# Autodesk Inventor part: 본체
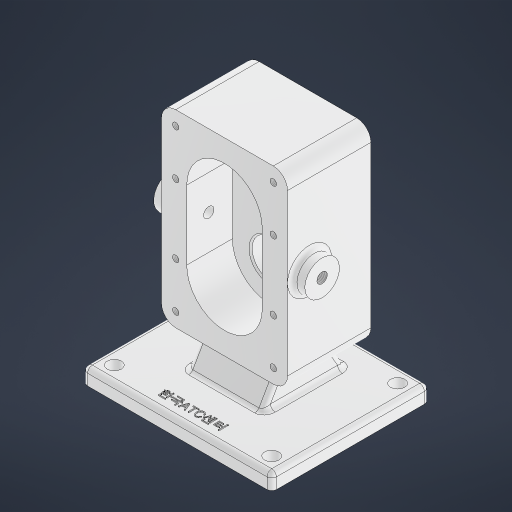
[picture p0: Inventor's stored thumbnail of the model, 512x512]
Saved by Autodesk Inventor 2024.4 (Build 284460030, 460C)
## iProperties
Created: 2026-10
Part Number: 본체
Material: 알루미늄 6061
Document SubType Name: Modeling
Designer: user
Density: 2.7 g/cm^3
Appearance: 알루미늄 - 평지
Mass: 1476.64 g
Surface Area: 830.225 cm^2
Volume: 546.904 cm^3
Author: user
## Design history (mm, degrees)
sketch "스케치1"
  geometry: L1 (-40, -26.5)-(40, -26.5); L2 (40, -26.5)-(40, 26.5); L3 (40, 26.5)-(-40, 26.5); L4 (-40, 26.5)-(-40, -26.5); L5 (-40, -26.5)-(40, 26.5); L6 (40, -26.5)-(-40, 26.5); 1 further point
  constraints: 12 end point, 2 midpoint, 2 parallel, 1 horizontal, 1 perpendicular
  dimensions: "d2" = 80 distance of L3.end L2.end; "d3" = 53 distance of L2.end L1.end
extrude "돌출1" new body sketch "스케치1" stored distance "d4" = 120; taper "d5" = 0 deg
fillet "모깎기1" dims "d6" = 9
sketch "스케치2"
  geometry: L1 (31, 38)-(31, 82); L2 (7, 38)-(7, 82); L3 (55, 82)-(55, 38); A1 r 24 centre (31, 38) between (7, 38) and (55, 38); A2 r 24 centre (31, 82) between (55, 82) and (7, 82); 3 further points
  constraints: 8 end point, 6 point on circle, 4 tangent, 2 centre point, 1 midpoint, 1 parallel, 1 vertical
  dimensions: "d7" = 48 distance between parallel lines of L2 L3; "d8" = 92 distance of point (31, 14) point (31, 106)
extrude "돌출2" cut sketch "스케치2" distance "d9" = 29; taper "d10" = 0 deg
sketch "스케치3"
  geometry: C1 r 12.5 at (31, 82); C2 r 12.5 at (31, 38); A1 r 24 centre (31, 38) between (7, 38) and (55, 38) reference; A2 r 24 centre (31, 82) between (55, 82) and (7, 82) reference; 1 further point
  constraints: 2 centre point, 2 coincident
  dimensions: "d11" = 25 diameter of C1; "d12" = 25 diameter of C2
extrude "돌출3" cut sketch "스케치3" distance "d13" = 15; taper "d14" = 0 deg
sketch "스케치4"
  geometry: C1 r 12.5 at (31, 38) reference; C2 r 19 at (31, 38); 1 further point
  constraints: 1 centre point, 1 coincident
  dimensions: "d15" = 38 diameter of C2
extrude "돌출4" join sketch "스케치4" distance "d16" = 17; taper "d17" = 0 deg
sketch "스케치5"
  geometry: C1 r 19 at (0, 0) reference; C2 r 14 at (0, 0); 1 further point
  constraints: 1 centre point, 1 coincident
  dimensions: "d18" = 28 diameter of C2
extrude "돌출5" cut sketch "스케치5" distance "d19" = 7.3; taper "d20" = 0 deg
sketch "스케치6"
  geometry: C1 r 12.5 at (0, 0) reference; C2 r 8.5 at (0, 0); 1 further point
  constraints: 1 centre point, 1 coincident
  dimensions: "d21" = 17 diameter of C2
extrude "돌출6" cut sketch "스케치6" distance "d22" = 29; taper "d23" = 0 deg
node "작업 평면1"
sketch "스케치9"
  geometry: L1 (19, 43.5)-(-19, 43.5) reference; L2 (60, -56.5)-(-60, -56.5); L3 (-60, -56.5)-(-60, 43.5); L4 (-60, 43.5)-(60, 43.5); L5 (60, 43.5)-(60, -56.5); L6 (60, -56.5)-(-60, 43.5); L7 (-60, -56.5)-(60, 43.5); 5 further points
  constraints: 12 end point, 4 midpoint, 2 parallel, 1 horizontal, 1 perpendicular, 1 vertical alignment
  dimensions: "d28" = 120 distance of L3.end L4.end; "d29" = 100 distance of L2.end L3.end
extrude "돌출7" join sketch "스케치9" distance "d30" = 10; taper "d31" = 0 deg
sketch "스케치10"
  geometry: L1 (-26.5, -60)-(26.5, -60) reference; L2 (-56.5, -80)-(43.5, -80) reference; L3 (43.5, -80)-(-56.5, -80) reference; L4 (-14.953, -60)-(-26.5, -80); L5 (14.953, -60)-(26.5, -80); L6 (43.5, -90)-(43.5, -80) reference; 3 further points
  constraints: 4 end point, 4 point on line
  dimensions: "d32" = 60 deg angle of L2 L4; "d33" = 60 deg angle of L2 L5; "d34" = 53 distance of L5.end L4.end; "d35" = 17 distance from line of L6 L5.end
extrude "돌출8" join sketch "스케치10" stored distance "d36" = 48; taper "d37" = 0 deg
sketch "스케치11"
  geometry: L1 (-102, 0)-(0, 0) reference; C1 r 11 at (-51, 14); 1 further point
  constraints: 1 centre point, 1 vertical alignment
  dimensions: "d39" = 22 diameter of C1; "d40" = 14 distance from line of L1 C1.centre
extrude "돌출9" join sketch "스케치11" distance "d41" = 8; taper "d42" = 0 deg
sketch "스케치12"
  geometry: L1 (60, -56.5)-(60, 43.5) reference; L2 (60, 43.5)-(-60, 43.5) reference; C1 r 4.5 at (-50, 33.5); C2 r 4.5 at (50, 33.5); C3 r 4.5 at (-50, -46.5); C4 r 4.5 at (50, -46.5); 1 further point
  constraints: 4 centre point, 2 horizontal alignment, 2 vertical alignment
  dimensions: "d43" = 9 diameter of C1; "d44" = 9 diameter of C2; "d45" = 9 diameter of C3; "d46" = 9 diameter of C4; "d47" = 100 distance of C2.centre C1.centre; "d48" = 10 distance from line of L1 C2.centre; "d49" = 80 distance of C4.centre C2.centre; "d50" = 10 distance from line of L2 C2.centre
fillet "모깎기2" dims "d51" = 3
fillet "모깎기3" dims "d52" = 3
hole "구멍1" sketch "스케치12" diameter "d53" = 9; stored, may be unused: countersink angle "d57" = 90 deg, drill point angle "d59" = 118 deg; dims "d54" = 6, "d55" = 10, "d56" = 5.5, "d58" = 8
sketch "스케치13"
  geometry: A1 r 9 centre (0, 9) between (-9, 9) and (0, 0) reference; A2 r 9 centre (62, 9) between (62, 0) and (71, 9) reference; A3 r 9 centre (62, 111) between (71, 111) and (62, 120) reference; 9 further points
  constraints: 4 vertical alignment, 3 coincident, 3 horizontal alignment
  dimensions: "d60" = 62 distance of point (62, 111) point (0, 111); "d61" = 29 distance of point (62, 82) point (62, 111); "d63" = 29 distance of point (62, 9) point (62, 38)
hole "구멍2" sketch "스케치13" at (0, 111), (62, 111), (62, 82), (0, 82), (0, 38), (62, 38), (62, 9), (0, 9) diameter "d64" = 4.134; stored, may be unused: countersink angle "d68" = 90 deg, drill point angle "d70" = 118 deg; dims "d65" = 10, "d66" = 5, "d67" = 2, "d69" = 12
sketch "스케치14"
  geometry: L1 (-57, -56.5)-(57, -56.5) reference; 2 further points
  constraints: 1 vertical alignment, 1 other
  dimensions: "d71" = 10 distance from line of point (0, -46.5) L1
sketch "스케치16"
  geometry: C1 r 11 at (0, 0) reference; 2 further points
  constraints: 1 coincident
hole "구멍3" sketch "스케치16" at (0, 0) diameter "d72" = 6.647; stored, may be unused: countersink angle "d76" = 90 deg, drill point angle "d78" = 0 deg; dims "d73" = 8, "d74" = 4, "d75" = 2, "d77" = 24
chamfer "모따기1" distance "d79" = 1; stored, may be unused: second distance "d80" = 2, angle "d81" = 45 deg
fillet "모깎기4" dims "d82" = 0.5
chamfer "모따기2" distance "d83" = 0.7; stored, may be unused: second distance "d84" = 2, angle "d85" = 30 deg
feature "엠보싱1" dims "d2" = 80, "d3" = 53, "d86" = 0.5, "d87" = 0
fillet "모깎기5" dims "d88" = 3
fillet "모깎기6" dims "d89" = 3
sketch "스케치17"
  geometry: C1 r 11 at (0, 0) reference; 2 further points
  constraints: 1 coincident
hole "구멍4" sketch "스케치17" at (0, 0) diameter "d90" = 6.647; stored, may be unused: countersink angle "d94" = 90 deg, drill point angle "d96" = 0 deg; dims "d91" = 8, "d92" = 4, "d93" = 2, "d95" = 24
node "솔리드1"
mirror "미러1"
node "투영된 루프1"
node "투영된 루프2"
